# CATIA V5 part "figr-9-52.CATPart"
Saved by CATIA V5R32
Part number: Part1
Bounding box of the stored display mesh (mm): x -121 to 121, y -90 to 90, z -40 to 40
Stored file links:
  D:\PROJECTS\Project 2022\CATIA V5 6R 2022\Resources\Part Files\c09_catia_v5_6r2022_prt\c09_catia_v5_6r2022_prt\figr-9-52.CATPart
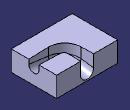
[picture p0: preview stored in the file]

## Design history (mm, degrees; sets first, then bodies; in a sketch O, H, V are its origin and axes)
Body1 (main body)
  Sketch1 on yz-plane, origin (0, 0, 0), H (0, 1, 0), V (0, 0, 1)
    line L1 (-90, 40) -> (90, 40)
    line L2 (90, 40) -> (90, -40)
    line L3 (90, -40) -> (-90, -40)
    line L4 (-90, -40) -> (-90, 40)
    axis line L5 (90, -40) -> (-90, 40)
    horizontal: L1 H, L3 H
    vertical: L2 V, L4 V
    midpoint: O L5
  Pad1: profile Sketch1, direction (1, 0, 0), length 121, mirrored extent
  Loft1: solid, Sections (Sketch4; Sketch3), Spine Sketch2, SectionCouplingPoints ({coupling CouplingPoints (vertex [element of Sketch4 | element of Sketch4]; vertex [element of Sketch3 | element of Sketch3])}; {coupling CouplingPoints (vertex [element of Sketch4 | element of Sketch4]; vertex [element of Sketch3 | element of Sketch3])}; {coupling CouplingPoints (vertex [element of Sketch4 | element of Sketch4]; vertex [element of Sketch3 | element of Sketch3])})
  Sketch2 on face of Pad1, origin (0, 0, 40), H (1, 0, 0), V (0, 1, 0)
    point P1 (121, 0)
    line L1 (121, 0) -> (40.984, 0)
    arc A1 centre (40.984, 40.984) radius 40.984 from (40.984, 0) to (0, 40.984) cw
    line L2 (0, 40.984) -> (0, 90)
    point P5 (0, 90)
    reference projected line E1 (121, 20) -> (121, -20) from edge of Sketch4
    reference projected line E2 (-25.9516, 90) -> (25.9516, 90) from edge of Sketch3
    coincidence: P1 H, P1 E1, P5 E2
    horizontal: L1 H
    tangency: A1 L1, L2 A1
    vertical: L2 V
  Sketch3 on face of Pad1, origin (0, 90, 0), H (-1, 0, 0), V (0, 0, 1)
    line L1 (-25.9516, 40) -> (-25.9516, -8.0968)
    arc A1 centre (0, -8.0968) radius 25.9516 from (-25.9516, -8.0968) to (25.9516, -8.0968) ccw
    point P3 (0, -8.0968)
    line L2 (25.9516, -8.0968) -> (25.9516, 40)
    line L3 (25.9516, 40) -> (-25.9516, 40)
    reference projected line E1 (121, 40) -> (-121, 40) from edge [face of Pad1 | face of Pad1]
    vertical: L1 V, L2 V
    tangency: A1 L1, L2 A1
    horizontal: L3 H
    coincidence: P3 V, L3 E1
  Sketch4 on face of Pad1, origin (121, 0, 0), H (0, 1, 0), V (0, 0, 1)
    line L1 (-20, 40) -> (-20, 21.9917)
    arc A1 centre (0, 21.9917) radius 20 from (-20, 21.9917) to (20, 21.9917) ccw
    point P3 (0, 21.9917)
    line L2 (20, 21.9917) -> (20, 40)
    line L3 (20, 40) -> (-20, 40)
    reference projected line E1 (90, 40) -> (-90, 40) from edge [face of Pad1 | face of Pad1]
    vertical: L1 V, L2 V
    tangency: A1 L1, L2 A1
    horizontal: L3 H
    coincidence: P3 V, L3 E1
